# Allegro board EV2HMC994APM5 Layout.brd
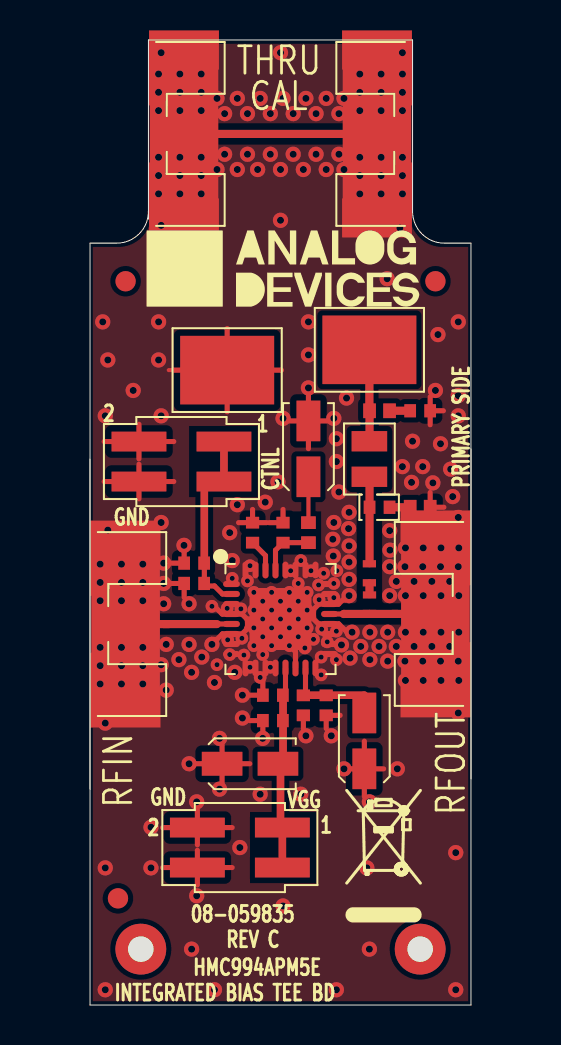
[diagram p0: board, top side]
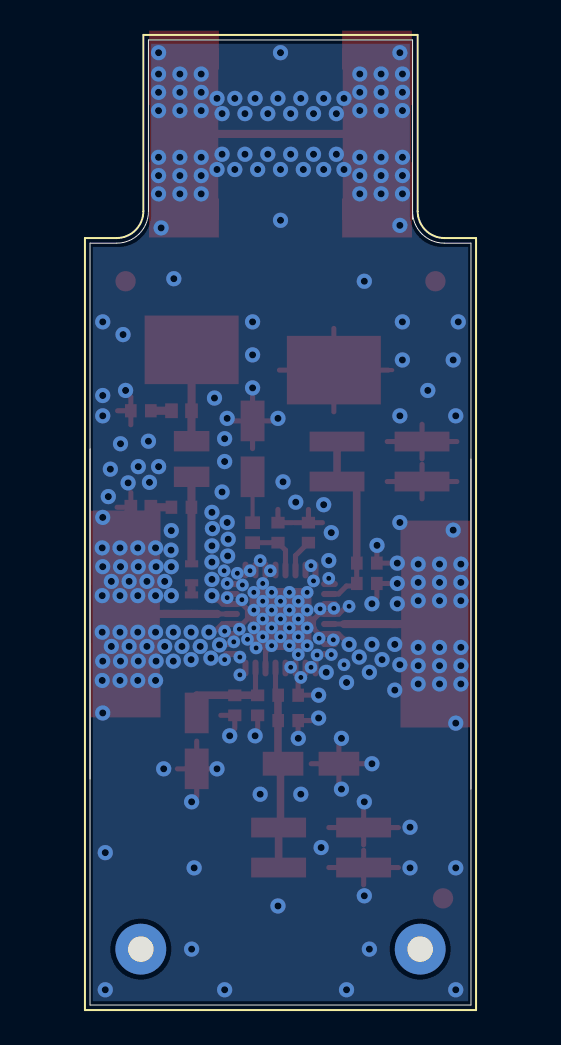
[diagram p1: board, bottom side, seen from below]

Outline 19.05 x 48.26 mm; copper layers: TOP, BOTTOM. Coordinates in mm from the lower left corner of the outline.
Outline path: 0,38.1 1.33,38.1 arc(2.46,38.56) 2.92,39.69 2.92,48.26 16.13,48.26 16.13,39.69 arc(16.59,38.56) 17.72,38.1 19.05,38.1 19.05,0 0,0 0,38.1

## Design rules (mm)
constraint set DEFAULT: min track width 0.203
net group RF: nets UNNAMED_2_ADHMC994V2_I1_RFIN UNNAMED_2_ADHMC994V2_I1_RFOUT
net group RF_E: nets RFIN RFOUT UNNAMED_2_CNBNC4P_I34_CNTR

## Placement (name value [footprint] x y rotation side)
AGND  5016  [CNKEY5016TP]  6.86 31.75 180 top
C1  100PF  [C0402]  8.13 23.62 90 top
C2  100PF  [C0402]  5.21 21.08 0 top
C3  100PF  [C0402]  9.14 15.49 0 top
C4  100PF  [C0402]  10.67 14.99 90 top
C5  0.01UF  [C0402]  9.65 23.62 270 top
C6  0.01UF  [C0402]  5.21 22.1 0 top
C7  0.01UF  [C0402]  9.14 14.22 0 top
C8  0.01UF  [C0402]  11.81 14.99 90 top
C9  4.7uF  [C3216]  10.92 27.81 90 top
C10  4.7uF  [C3216]  13.72 13.21 90 top
C11  4.7uF  [C3216]  8 12.06 0 top
C12  100PF  [C0402H22]  14.46 24.89 0 top
C13  0.01UF  [C0402]  16.51 29.72 0 top
CIN  0.1UF  [C0402]  3.18 19.05 0 top
COUT  0.1UF  [C0402]  15.88 19.56 0 top
J1  25-146-1000-92  [CNK38G62THK_EDGE]  0 19.05 180 top
J2  25-146-1000-92  [CNK38G62THK_EDGE]  19.05 19.56 0 top
J3  87759-0414  [CNSMMHDR2X2L156W157H272]  4.57 27.18 270 top
J4  87759-0414  [CNSMMHDR2X2L156W157H272]  7.49 7.87 270 top
J5  25-146-1000-92  [CNK38G62THK_EDGE]  16.13 43.56 0 top
J6  25-146-1000-92  [CNK38G62THK_EDGE]  2.92 43.56 180 top
L1  56NH  [L0402-2]  13.98 19.98 90 top
L2  56NH  [L0402-2#2]  13.97 21.59 90 top
L3  1uH  [L9075]  13.97 27.3 90 top
NOREF  -  []  2.54 2.79 0 top
NOREF#2  -  []  19.3 19.56 0 top
NOREF#3  -  [unnamed#2]  17.27 36.19 0 top
NOREF#4  -  []  0 38.1 0 top
NOREF#5  -  []  0 0 90 top
NOREF#6  -  [unnamed#2]  16.51 2.79 0 top
NOREF#7  -  []  -215.98 150.09 0 top
NOREF#8  -  []  -81.03 -172.85 0 top
NOREF#9  -  []  -269.88 -336.3 0 top
NOREF#10  -  []  16.65 38.51 0 top
NOREF#11  -  [unnamed#2]  2.54 2.79 0 top
NOREF#12  -  []  -56.9 -78.61 0 top
NOREF#13  -  []  9.53 36.83 0 top
NOREF#14  -  []  -139.45 66.67 0 top
NOREF#15  -  []  -212.27 127.23 0 top
NOREF#16  -  []  9.65 61.59 0 top
NOREF#17  -  [unnamed#2]  1.78 36.19 0 top
NOREF#18  -  []  -72.03 -178.42 0 top
NOREF#19  -  []  0 0 0 top
NOREF#20  -  []  2.54 2.79 0 top
NOREF#21  -  []  0 0 90 top
NOREF#22  -  []  61.11 -160.73 0 top
NOREF#23  -  []  -159.77 -245.36 0 top
NOREF#24  -  []  14.48 4.19 0 top
NOREF#25  -  []  -178.94 -91.19 0 top
NOREF#26  -  []  56.26 88.27 0 top
NOREF#27  -  []  -212.22 104.37 0 top
NOREF#28  -  []  136.78 141.15 0 top
NOREF#29  -  []  0 0 0 top
NOREF#30  -  []  0 38.1 90 top
NOREF#31  -  [unnamed#2]  1.4 5.33 0 top
NOREF#32  -  []  0 38.1 0 top
NOREF#33  -  []  9.53 19.05 90 bottom
NOREF#34  -  []  -31.62 58.55 180 bottom
R1  0  [R0402]  10.92 23.62 90 top
R2  0  [R0402]  14.48 29.72 0 top
R3  340  [R0402]  16.51 24.89 0 top
U1  HMC994APM5E  [QFN32_5X5_PAD3_1X3_1_A]  9.53 19.3 270 top
VDD  5016  [CNKEY5016TP]  13.97 32.77 180 top

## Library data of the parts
AGND VDD = CNTP1P: Tolerance: N/A; User Part Number: UPN; alternate symbols: (); part number: CNTP1P_SM-5016,E005890,CNKEY5016TP; tolerance: N/A
C1-C4 = CAP: User Part Number: UPN; Tolerance: 5; alternate symbols: (); part number: CAP_SM-100PF,50V,5,E033811,C0402; tolerance: 5
C5-C8 C13 = CAP: User Part Number: UPN; Tolerance: 10; alternate symbols: (); part number: CAP_SM-0.01UF,100V,10,E032295,C0402; tolerance: 10
C9-C11 = CAPP: Tolerance: N/A; User Part Number: UPN; alternate symbols: (); part number: CAPP_SM-4.7UF,N/A,N/A,E000691,C3216; tolerance: N/A
C12 = CAP: Tolerance: 5; User Part Number: UPN; alternate symbols: (); part number: CAP_SM-100PF,50V,5,E025263,C0402H22; tolerance: 5
CIN COUT = CAP: User Part Number: UPN; Tolerance: 10; alternate symbols: (); part number: CAP_SM-0.1UF,16V,10,E024454,C0402; tolerance: 10
J1 J2 J5 J6 = CNBNC4P: Tolerance: N/A; User Part Number: UPN; alternate symbols: (CNK38G62THK_EDGE_HMC84X3,CNK40G62THK-SRI-SW_EDGE,CNK38G62THK_EDGE_ADMV1014,CNK38G62THK_EDGE_ADL81XX); part number: CNBNC4P_SM-25-146-1000-92,E023346,CNK38G62THK_EDGE; tolerance: N/A
J3 J4 = CN4P_ODD_EVEN: User Part Number: UPN; Tolerance: N/A; alternate symbols: (); part number: CN4P_ODD_EVEN_SM-87759-0414,E026270,CNSMMHDR2X2L156W157H272; tolerance: N/A
L1 L2 = IND: Tolerance: 5; User Part Number: UPN; alternate symbols: (); part number: IND_SM-56NH,5,E040186,L0402-2; tolerance: 5
L3 = IND: Tolerance: 5; User Part Number: UPN; alternate symbols: (); part number: IND_SM-1UH,5,E010060,L9075; tolerance: 5
R1 R2 = RES: User Part Number: UPN; Tolerance: 5; alternate symbols: (R0402L,R0402L_ALT); part number: RES_SM-0,E003438,N/A,5,R0402; tolerance: 5
R3 = RES: User Part Number: UPN; Tolerance: 0.1; alternate symbols: (); part number: RES_SM-340,E031767,1/16W,0.1,R0402; tolerance: 0.1
U1 = ADHMC994_V2: User Part Number: UPN; Tolerance: N/A; alternate symbols: (); part number: ADHMC994_V2_SM-HMC994APM5E,E027751,QFN32_5X5_PAD3_1X3_1_A; tolerance: N/A

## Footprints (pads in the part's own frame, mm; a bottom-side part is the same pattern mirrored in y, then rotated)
C0402
  rect 0.584x0.66 smd: 1(-0.5,0) 2(0.5,0)
C0402H22
  rect 0.584x0.66 smd: 1(-0.479,0) 2(0.521,0)
C3216
  rect 2.032x1.194 smd: N(1.397,0) P(-1.397,0)
CNK38G62THK_EDGE
  custom 0.102x0.102 smd: 1(-1.549,0)
  custom 0.873x0.873 smd: 2(-1.778,-3.302) 3(-1.778,3.302)
  rect 3.429x8.56 smd: 4(-1.778,0)
CNKEY5016TP
  rect 4.699x3.429 smd: 1(0,0)
CNSMMHDR2X2L156W157H272
  rect 0.991x2.743 smd: 1(-1,2.125) 2(-1,-2.125) 3(1,2.125) 4(1,-2.125)
L0402-2
  rect 0.406x0.66 smd: 1(-0.419,0)
  rect 0.356x0.66 smd: 2(0.531,0)
L0402-2#2
  rect 0.356x0.66 smd: 1(-0.475,0) 2(0.475,0)
L9075
  rect 1.016x1.778 smd: 1(-0.889,0) 2(0.889,0)
QFN32_5X5_PAD3_1X3_1_A
  oval 0.305x0.838 smd: 1(-1.75,-2.45) 2(-1.25,-2.45) 3(-0.75,-2.45) 4(-0.25,-2.45) 5(0.25,-2.45) 6(0.75,-2.45) 7(1.25,-2.45) 8(1.75,-2.45) 17(1.75,2.45) 18(1.25,2.45) 19(0.75,2.45) 20(0.25,2.45) 21(-0.25,2.45) 22(-0.75,2.45) 23(-1.25,2.45) 24(-1.75,2.45)
  oval 0.838x0.305 smd: 9(2.45,-1.75) 10(2.45,-1.25) 11(2.45,-0.75) 12(2.45,-0.25) 13(2.45,0.25) 14(2.45,0.75) 15(2.45,1.25) 16(2.45,1.75) 25(-2.45,1.75) 26(-2.45,1.25) 27(-2.45,0.75) 28(-2.45,0.25) 29(-2.45,-0.25) 30(-2.45,-0.75) 31(-2.45,-1.25) 32(-2.45,-1.75)
  rect 3.099x3.099 smd: PAD(0,0)
R0402
  rect 0.635x0.737 smd: 1(-0.5,0) 2(0.5,0)
unnamed#2
  round 1.016 smd: (0,0)

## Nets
AGND: AGND.1(N1) C1.2(N2) C2.1 C3.1 C4.1 C5.1 C6.1 C7.1 C8.1 C9.N(N2) C10.P C11.P C13.2(N2) J1.2 J1.3 J1.4(SH3) J2.2 J2.3 J2.4(SH3) J3.2 J3.4(N4) J4.2 J4.4(N4) J5.2 J5.3 J5.4(SH3) J6.2 J6.3 J6.4(SH3) R3.2(N2) U1.1 U1.3 U1.4 U1.6 U1.7 U1.8 U1.9 U1.10 U1.11 U1.12 U1.14 U1.16 U1.17 U1.18 U1.19 U1.20 U1.22 U1.23 U1.24 U1.25 U1.26 U1.27 U1.28 U1.31 U1.32 U1.PAD
VDD: L3.2(N2) R2.1 VDD.1(N1)
CNTL: C2.2(N2) C6.2(N2) J3.1 J3.3 U1.2(VGG2)
RFIN: CIN.1 J1.1
RFOUT: COUT.2(N2) J2.1
UNNAMED_2_ADHMC994V2_I1_ACG1: C1.1 U1.30
UNNAMED_2_ADHMC994V2_I1_ACG2: C5.2(N2) R1.1 U1.29
UNNAMED_2_ADHMC994V2_I1_ACG3: C4.2(N2) C8.2(N2) C10.N(N2) U1.15
UNNAMED_2_ADHMC994V2_I1_RFIN: CIN.2(N2) U1.5
UNNAMED_2_ADHMC994V2_I1_RFOUT: COUT.1 L1.1 U1.21
UNNAMED_2_CAP_I56_N1: C12.1 L2.2(N2) L3.1
UNNAMED_2_CAP_I56_N2: C12.2(N2) R3.1
UNNAMED_2_CAP_I57_N1: C13.1 R2.2(N2)
UNNAMED_2_CAPP_I23_N1: C9.P R1.2(N2)
UNNAMED_2_CNBNC4P_I34_CNTR: J5.1 J6.1
UNNAMED_2_IND_I40_N2: L1.2(N2) L2.1
VGG: C3.2(N2) C7.2(N2) C11.N(N2) J4.1 J4.3 U1.13

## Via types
v1: diameter 0.762, hole 0.356, TOP to BOTTOM, 224 vias
v2: diameter 0.635, hole 0.254, TOP to BOTTOM, 57 vias

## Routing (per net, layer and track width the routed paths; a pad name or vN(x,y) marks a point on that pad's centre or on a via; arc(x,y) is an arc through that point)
AGND: length 73.2
  TOP w0.203: 4.14,31.75 3.94,31.75
  TOP w0.254: C9.N 11.89,29.21 ; C9.N 10.92,30.59 ; C9.N 9.96,29.21 ; C9.N 10.92,27.83 ; 4.71,22.8 C6.1 4.05,22.1 ; 11.81,13.82 C8.1 12.51,14.49 ; R3.2 17.7,24.89 ; R3.2 17.01,25.63 ; R3.2 17.01,24.15 ; C13.2 17.67,29.72 ; C13.2 17.01,29.02 ; C13.2 17.01,30.42 ; 10.67,13.82 C4.1 ; 0.71,26.18 J3.4 ; J3.4 4.19,26.18 ; J3.4 2.45,25.31 ; J3.4 2.45,27.04 ; v2(12.19,20.37) 12.19,20.05 ; 12.19,20.05 12.43,20.05 12.64,20.26 12.74,20.26 v1(12.95,20.47) ; 12.19,20.05 11.98,20.05 ; AGND.1 9.58,31.75 ; AGND.1 4.14,31.75 ; AGND.1 6.86,33.83 ; AGND.1 6.86,29.67 ; J4.2 5.37,9.74 ; J4.2 5.37,8.01 ; J4.2 3.63,8.87 ; J4.2 7.11,8.87 ; 6.6,11.1 6.6,12.06 ; 6.6,12.06 5.22,12.06 ; 6.6,12.06 6.6,13.03 ; 6.6,12.06 7.99,12.06 ; C10.P 14.68,11.81 ; C10.P 12.75,11.81 ; C10.P 13.72,13.2 ; C10.P 13.72,10.43 ; 7.85,18.86 7.85,18.8 7.61,18.56 7.07,18.56 ; 7.85,18.86 7.87,18.88 7.87,19.28 7.85,19.3 ; 7.85,18.86 v2(8.19,18.86) ; 7.85,19.3 7.6,19.55 7.07,19.55 ; 7.85,19.3 v2(8.64,19.3) v2(9.53,19.3) ; v2(9.97,17.97) 10.28,17.66 U1.14 ; 5.37,6.01 J4.4 ; J4.4 5.37,7.74 ; J4.4 7.11,6.87 ; J4.4 3.63,6.87 ; C1.2 8.83,24.12 ; C1.2 7.43,24.12 ; C1.2 8.13,24.78 ; v1(13.11,18.64) 13,18.54 12.95,18.54 12.43,19.06 11.42,19.06 11.18,19.3 11.18,19.79 11.44,20.05 11.98,20.05 ; 4.05,21.08 C2.1 4.71,20.38 ; 11.98,20.05 U1.22 ; J3.2 4.19,28.18 ; J3.2 0.71,28.18 ; J3.2 2.45,29.04 ; J3.2 2.45,27.31 ; U1.6 7.07,18.56 ; 7.07,18.56 6.62,18.56 6.35,18.29 6.1,18.29 v1(6.1,18.03) ; 8.95,24.12 9.65,24.12 9.65,24.78 ; 7.98,15.49 C3.1 8.64,16.19 ; v2(6.1,19.94) 6.22,19.94 6.61,19.55 7.07,19.55 ; 7.98,14.22 C7.1 8.64,13.52 ; 7.07,19.55 U1.4 ; v2(10.86,19.75) 11,19.61
  vias: v1(0.51,22.05) v1(0.51,21.13) v1(0.51,20.22) v1(0.51,17.88) v1(0.51,16.97) v1(0.51,16.06) v1(0.64,34.16) v1(0.76,29.46) v1(0.76,14.1) v1(0.76,6.86) v1(0.76,0.76) v1(0.89,32.26) v1(0.89,23.75) v1(1.57,22.05) v1(1.57,21.13) v1(1.57,20.22) v1(1.57,17.88) v1(1.57,16.97) v1(1.57,16.06) v1(2.16,30.73) v1(2.64,22.05) v1(2.64,21.13) v1(2.64,20.22) v1(2.64,17.88) v1(2.64,16.97) v1(2.64,16.06) v1(3.05,8.89) v1(3.05,6.86) v1(3.43,46.56) v1(3.43,45.64) v1(3.43,44.73) v1(3.43,42.4) v1(3.43,41.48) v1(3.43,40.57) v1(3.43,34.16) v1(3.43,32.26) v1(3.56,47.62) v1(3.56,38.99) v1(3.56,29.46) v1(3.56,24.13) v1(3.56,17.02) v1(3.68,22.1) v1(3.68,21.08) v1(3.68,20.07) v1(3.81,18.03) v1(3.81,15.75) v1(4.45,17.27) v1(4.49,46.56) v1(4.49,45.64) v1(4.49,44.73) v1(4.49,42.4) v1(4.49,41.48) v1(4.49,40.57) v1(4.7,22.99) v1(4.95,20.07) v1(4.95,18.03) v1(4.95,12.06) v1(5.08,16.64) v1(5.08,2.79) v1(5.33,36.19) v1(5.33,10.16) v1(5.33,5.46) v1(5.56,46.56) v1(5.56,45.64) v1(5.56,44.73) v1(5.56,42.4) v1(5.56,41.48) v1(5.56,40.57) v1(5.59,17.4) v1(6.22,16.13) v1(6.22,0.76) v1(6.35,45.34) v1(6.35,41.78) v1(6.48,13.33) v1(6.48,10.79) v1(6.73,44.58) v1(6.73,42.55) v1(6.99,23.62) v1(7.11,22.22) v1(7.24,16.64) v1(7.37,45.34) v1(7.37,41.78) v1(7.37,25.02) v1(7.49,7.87) v1(7.62,15.49) v1(7.62,14.35) v1(7.87,44.58) v1(7.87,42.55) v1(8.38,41.78) v1(8.51,45.34) v1(8.51,10.54) v1(8.64,13.33) v1(8.76,25.15) v1(9.02,44.58) v1(9.02,42.55) v1(9.4,26.16) v1(9.53,47.62) v1(9.53,41.78) v1(9.53,39.24) v1(9.65,45.34) v1(9.65,29.34) v1(9.65,4.95) v1(10.16,44.58) v1(10.16,42.55) v1(10.54,10.54) v1(10.67,41.78) v1(10.8,45.34) v1(10.8,13.46) v1(10.92,34.16) v1(10.92,32.51) v1(10.92,30.86) v1(11.3,44.58) v1(11.3,42.55) v1(11.81,45.34) v1(11.81,41.78) v1(12.07,13.46) v1(12.14,23.29) v1(12.17,22.45) v1(12.19,29.34) v1(12.19,24.13) v1(12.32,28.32) v1(12.32,27.18) v1(12.32,0.76) v1(12.45,44.58) v1(12.45,42.55) v1(12.45,25.65) v1(12.57,18.01) v1(12.7,45.34) v1(12.7,41.78) v1(12.7,11.81) v1(12.83,30.35) v1(12.95,24.64) v1(12.93,23.83) v1(12.95,22.96) v1(12.95,22.15) v1(12.95,21.29) v1(13,17.35) v1(13.49,46.56) v1(13.49,45.64) v1(13.49,44.73) v1(13.49,42.39) v1(13.49,41.48) v1(13.49,40.56) v1(13.54,17.93) v1(13.84,6.86) v1(13.97,10.16) v1(13.97,2.79) v1(14,18.64) v1(14,17.27) v1(14.45,17.93) v1(14.56,46.56) v1(14.56,45.64) v1(14.56,44.73) v1(14.56,42.39) v1(14.56,41.48) v1(14.56,40.56) v1(14.86,36.32) v1(14.88,18.64) v1(14.88,17.2) v1(14.99,23.72) v1(15,22.75) v1(14.99,21.92) v1(14.99,20.47) v1(15.32,21.18) v1(15.32,17.93) v1(15.37,11.81) v1(15.49,38.86) v1(15.62,47.62) v1(15.62,46.56) v1(15.62,45.64) v1(15.62,44.73) v1(15.62,42.39) v1(15.62,41.48) v1(15.62,40.56) v1(15.62,26.92) v1(15.77,22.86) v1(15.75,21.92) v1(15.77,20.47) v1(15.77,18.64) v1(15.75,17.2) v1(15.77,16.23) v1(16.13,28.19) v1(16.08,26.14) v1(16.21,21.18) v1(16.21,17.93) v1(16.64,26.92) v1(16.66,22.86) v1(16.64,21.92) v1(16.66,20.47) v1(16.66,18.64) v1(16.64,17.2) v1(16.66,16.23) v1(17.15,26.11) v1(17.09,21.18) v1(17.09,17.93) v1(17.27,30.73) v1(17.4,33.53) v1(17.53,28.07) v1(17.55,22.86) v1(17.53,21.92) v1(17.55,20.47) v1(17.55,18.64) v1(17.53,17.2) v1(17.55,16.23) v1(18.03,26.8) v1(17.98,21.18) v1(17.98,17.93) v1(18.14,25.43) v1(18.29,7.62) v1(18.29,0.76) v1(18.42,34.16) v1(18.42,30.48) v1(18.42,29.46) v1(18.42,24.38) v1(18.44,22.86) v1(18.42,21.92) v1(18.44,20.47) v1(18.44,18.64) v1(18.42,17.2) v1(18.44,16.23) v1(18.42,14.6) v2(6.35,17.02) v2(6.86,19.84) v2(6.88,18.26) v2(6.99,17.53) v2(7.11,21.34) v2(7.54,19.81) v2(7.59,18.34) v2(7.7,17.5) v2(7.87,21.21) v2(8,21.97) v2(8,16.89) v2(8.19,20.64) v2(8.19,19.75) v2(8.19,17.97) v2(8.51,16.38) v2(8.64,20.19) v2(8.64,18.41) v2(8.64,17.53) v2(9.02,16.89) v2(9.08,20.64) v2(9.08,19.75) v2(9.08,18.86) v2(9.08,17.97) v2(9.53,20.19) v2(9.53,18.41) v2(9.97,20.64) v2(9.97,19.75) v2(9.97,18.86) v2(10.03,21.72) v2(10.41,21.08) v2(10.41,20.19) v2(10.41,19.3) v2(10.41,18.41) v2(10.54,22.22) v2(10.74,17.86) v2(10.86,20.64) v2(10.86,18.86) v2(11.05,21.72) v2(11.18,18.29) v2(11.43,21.01) v2(11.46,20.27) v2(11.56,17.4) v2(11.56,16.51) v2(11.58,18.8) v2(11.68,21.59) v2(11.86,18.16) v2(12.19,21.08) v2(12.34,21.72) v2(12.32,18.69) v2(12.32,17.27)
VDD: length 4.6
  TOP w0.406: VDD.1 13.97,29.73 R2.1 13.98,28.2 L3.2
CNTL: length 9.5
  TOP w0.254: U1.2 6.62,20.55 6.22,20.95 5.72,20.95 5.72,21.08 ; 5.72,21.08 5.72,22.1 ; 5.72,21.08 C2.2
  TOP w0.381: J3.1 J3.3 6.11,26.18 5.72,25.78 5.72,22.1 C6.2
RFIN: length 1.1
  TOP w0.406: J1.1 CIN.1
RFOUT: length 1.1
  TOP w0.406: J2.1 COUT.2
UNNAMED_2_ADHMC994V2_I1_ACG1: length 1.6
  TOP w0.254: U1.30 8.77,22.47 C1.1
UNNAMED_2_ADHMC994V2_I1_ACG2: length 2.8
  TOP w0.254: R1.1 C5.2 9.28,22.74 U1.29
UNNAMED_2_ADHMC994V2_I1_ACG3: length 5.5
  TOP w0.254: 10.77,15.59 U1.15 ; 10.77,15.59 10.77,15.51 10.8,15.49 ; 10.77,15.59 10.68,15.49
  TOP w0.381: 11.81,15.49 13.72,15.49 C10.N ; 11.81,15.49 C8.2 ; 11.81,15.49 10.68,15.49 C4.2
UNNAMED_2_ADHMC994V2_I1_RFIN: length 3.4
  TOP w0.254: U1.5 6.35,19.05 6.35,19.05
  TOP w0.406: CIN.2 6.35,19.05
UNNAMED_2_ADHMC994V2_I1_RFOUT: length 3.4
  TOP w0.254: U1.21 12.69,19.55
  TOP w0.406: COUT.1 L1.1 12.7,19.56 12.69,19.55
UNNAMED_2_CAP_I56_N1: length 4.4
  TOP w0.203: 13.98,22.1 13.97,22.09 L2.2
  TOP w0.406: 13.98,22.1 C12.1 13.98,26.41 L3.1
UNNAMED_2_CAP_I56_N2: length 1
  TOP w0.406: C12.2 R3.1
UNNAMED_2_CAP_I57_N1: length 1
  TOP w0.406: C13.1 R2.2
UNNAMED_2_CAPP_I23_N1: length 2.3
  TOP w0.203: R1.2 C9.P
UNNAMED_2_CNBNC4P_I34_CNTR: length 10.1
  TOP w0.406: J5.1 J6.1
UNNAMED_2_IND_I40_N2: length 0.6
  TOP w0.203: 13.98,21.08 13.97,21.09 L2.1 ; 13.98,20.55 L1.2
  TOP w0.406: 13.98,21.08 13.98,20.55
VGG: length 10.3
  TOP w0.254: U1.13 9.77,15.5 9.65,15.49
  TOP w0.381: 9.65,14.22 9.65,12.19 9.53,12.06 ; 9.65,14.22 C7.2 ; 9.65,14.22 9.65,15.49 C3.2 ; J4.3 J4.1 9.53,8.97 9.53,12.06 ; C11.N 9.53,12.06

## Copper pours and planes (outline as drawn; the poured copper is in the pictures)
AGND on TOP: 3.06,48.07 15.99,48.07 15.99,39.55 16.47,38.39 17.63,37.91 18.91,37.91 18.91,0.19 0.14,0.19 0.14,37.91 1.42,37.91 2.58,38.39 3.06,39.55 ; 2 cut-outs
AGND on BOTTOM: 18.91,0.19 18.91,37.91 17.63,37.91 16.47,38.39 15.99,39.55 15.99,48.07 3.06,48.07 3.06,39.55 2.58,38.39 1.42,37.91 0.14,37.91 0.14,0.19

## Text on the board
Board Geometry/Soldermask Bottom: SOLDERMASK-02
Ref Des/Silkscreen Top: GND | INTEGRATED BIAS TEE BD | 08-059835 | HMC994APM5E | REV C | VGG | CTNL | PRIMARY SIDE | THRU | CAL | RFIN | RFOUT
PAGE_OUTLINE: C | B | PER ECR-104366 | PER ECR-094367 | 20AUG21 | 14APR20 | D.OLIVER | IVAN SOC | INTEGRATED BIAS TEE BD
DIMENSION: ANALOG DEVICES | 600-01711-00-1 | 2X R.062 | 4 PLACES | SEE DETAIL X | SEE NOTE 15
DISPLAY_TOP: RO4350B 0.10 +/- 0.001 (CRITICAL) | ENIG (Electroless Nickel/Immersion Gold) | PER IPC-4552 LATEST REVISION | CONNECTING ALL 4 LAYERS. | 17.    BOARD TO HAVE EDGE PLATING AT CONNECTOR EDGE WHERE INDICATED | 16.    CRITICAL LINE WIDTH 0.016 +/- 0.001" PRIMARY SIDE. ADJUST PROCESS | TO ACHIEVE WIDTH. | 15.    THRU VIAS FILLED WITH NON-CONDUCTIVE EPOXY AND PLATED OVER. | COPLANAR ON PRIMARY SIDE WITHIN .001 INCH PRIOR TO FINAL PLATING.
User.19: I.SOC | 03OCT19 | PER ECR-094367 | PER ECR-104366 | D.OLIVER | B | C | 14APR20 | 20AUG21 | INTEGRATED BIAS TEE BD
User.22: FIGURE | SIZE | 10.0 | 14.0 | 50.0 | PLATED | NON-PLATED | FINISHED HOLES IN MILS | ALL UNITS ARE IN MILS | QTY | 57 | 224 | 2 | TOLERANCE/NOTES
